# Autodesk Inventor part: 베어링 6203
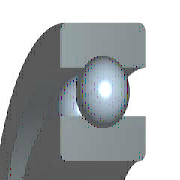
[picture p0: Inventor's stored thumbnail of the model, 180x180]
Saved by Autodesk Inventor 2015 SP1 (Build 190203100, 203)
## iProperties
IsCustomPart: 1
Company: 한국ATC센터
Created: 2009-02
Part Number: 베어링 6203
Material: 강, 연강
Description: 깊은 그루브 볼 베어링
Document SubType Name: Modeling
Standard: KS B 2023
Designer: KYOUNG IL JANG
Standards Organization: KS
Language: ko-KR
Size Designation: 6203 - 17 x 40 x 12
Categories: <MemberInstance><Categories><Category DisplayName="샤프트 부품" InternalName="7f7aeb1f-a693-4053-b835-cee3144e0d98" Mnemonic="SHFT"><Category DisplayName="베어링" Inter
Density: 1 g/cm^3
Appearance: 금속-강
Author: KYOUNG IL JANG
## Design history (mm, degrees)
sketch "스케치" dims "d0" = 5.98 (= -0.26 x WD + 0.26 x BD)
  geometry: L1 (3.01, 14.25)-(8.99, 14.25); L2 (6, 14.25)-(6, 11.26); L3 (6, 14.25)-(6, 17.24); L4 (3.778, 12.249)-(0, 12.249); L5 (0, 8.5)-(12, 8.5); L6 (3.778, 16.251)-(0, 16.251); L7 (0, 20)-(12, 20); L8 (12, 8.5)-(12, 12.249); L9 (8.222, 12.249)-(12, 12.249); L10 (8.222, 16.251)-(12, 16.251); L11 (12, 20)-(12, 16.251); L12 (-1.4, 0)-(8.4, 0) reference; L13 (0, -0.3)-(0, 5.3) reference
  constraints: 22 end point, 4 point on line, 2 collinear, 2 perpendicular, 2 symmetric about line, 1 midpoint, 1 parallel, 14 other
  dimensions: "d9" = 17 diameter of L5 L12 (= WD); "d11" = 40 diameter of L7 L12 (= BD); "d12" = 12 distance between parallel lines of L8 L13 (= KB); "d13" = 24.498 diameter of L9 L12 (= 0.326 x BD + 0.674 x WD)
revolve "본체" stored, may be unused: angle "d6" = 90 deg
revolve "볼" stored, may be unused: angle "d7" = 90 deg
pattern_circular "IDS_ARRAYBALL[SIMPL:T]" dims angle "d3" = 360 deg
body "Solid1"
fillet "모깎기1" dims "d1" = 0.6 (= KRS)
other parameters: "WD" = 17 [user parameter; used in 5 equation terms], "BD" = 40 [user parameter; used in 5 equation terms], "KB" = 12 [user parameter; used in 1 equation term], "KRS" = 0.6 [user parameter; used in 1 equation term], "d4" = 0, "d5" = 0, "d8" = 0, "d14" = 0, "d15" = 0, "BBA" = 0 [user parameter], "BC0" = 4750000 [user parameter], "BC" = 9560000 [user parameter], "WR" = 8.5 (= 0.5 x WD) [user parameter]
